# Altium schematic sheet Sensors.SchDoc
size A4
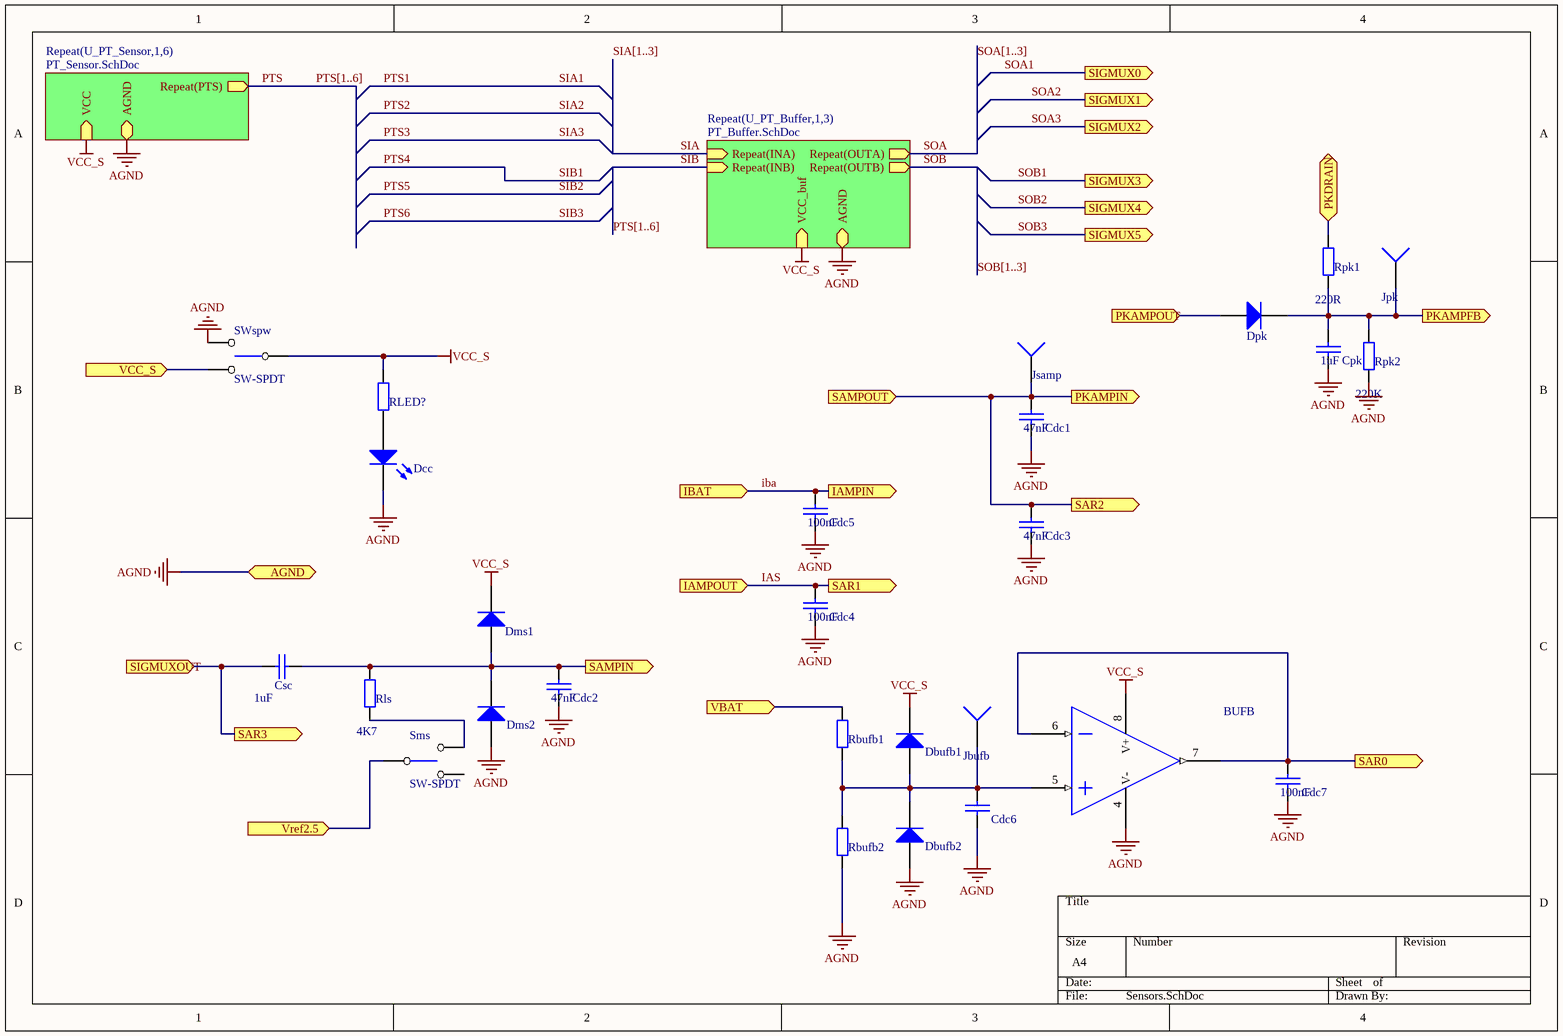
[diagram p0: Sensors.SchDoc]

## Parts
BUF  LT6221  [ECE-SO8]  (value not drawn)  (part B of 2)
Cdc1  47nF  [ECE-CAPC2012-0805SM]
Cdc2  47nF  [ECE-CAPC2012-0805SM]
Cdc3  47nF  [ECE-CAPC1608-0603SM]
Cdc4  100nF  [ECE-CAPC2012-0805SM]
Cdc5  100nF  [ECE-CAPC2012-0805SM]
Cdc6  100nF  [ECE-CAPC1608-0603SM]  (value not drawn)
Cdc7  100nF  [ECE-CAPC2012-0805SM]
Cpk  1uF  [ECE-CAPC1608-0603SM]
Csc  1uF  [ECE-CAPC2012-0805SM]
Dbufb1  1N4148  [ECE-DIO10.46-5.3x2.8TH]  (value not drawn)
Dbufb2  1N4148  [ECE-DIO10.46-5.3x2.8TH]  (value not drawn)
Dcc  LTST-C170KAKT  [ECE-LED2012-0805SM]  (value not drawn)
Dms1  1N4148  [ECE-DIO10.46-5.3x2.8TH]  (value not drawn)
Dms2  1N4148  [ECE-DIO10.46-5.3x2.8TH]  (value not drawn)
Dpk  1N4148  [ECE-DIO10.46-5.3x2.8TH]  (value not drawn)
Jbufb  TEST PIN  [ECE-HDR1TH]  (value not drawn)
Jpk  TEST PIN  [ECE-HDR1TH]  (value not drawn)
Jsamp  TEST PIN  [ECE-HDR1TH]  (value not drawn)
Rbufb1  47K  [ECE-RESC1608-0603SM]  (value not drawn)
Rbufb2  56K  [ECE-RESC2012-0805SM]  (value not drawn)
RLED?  270R  [ECE-RESC1608-0603SM]  (value not drawn)
Rls  4K7  [ECE-RESC2012-0805SM]
Rpk1  220R  [ECE-RESC1608-0603SM]
Rpk2  220K  [ECE-RESC1608-0603SM]
Sms  SW-SPDT  [SW-SPDT]
SWspw  SW-SPDT  [SW-SPDT]

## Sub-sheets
Repeat(U_PT_Buffer,1,3) = PT_Buffer.SchDoc: Repeat(INA) (in), Repeat(INB) (in), Repeat(OUTA) (out), Repeat(OUTB) (out), VCC_buf (in), AGND
Repeat(U_PT_Sensor,1,6) = PT_Sensor.SchDoc: Repeat(PTS) (out), VCC (in), AGND (bidir)

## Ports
AGND (bidir), IAMPIN (out), IAMPOUT (in), IBAT (in), PKAMPFB (out), PKAMPIN (out), PKAMPOUT (in), PKDRAIN (bidir), SAMPIN (out), SAMPOUT (in), SAR0 (out), SAR1 (out), SAR2 (out), SAR3 (out), SIGMUX0 (out), SIGMUX1 (out), SIGMUX2 (out), SIGMUX3 (out), SIGMUX4 (out), SIGMUX5 (out), SIGMUXOUT (in), VBAT (in), VCC_S (in), Vref2.5 (in)

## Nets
AGND: BUF.4(V-) Cdc1.2 Cdc2.2 Cdc3.2 Cdc4.2 Cdc5.2 Cdc6.2 Cdc7.2 Cpk.2 Dbufb2.1(A) Dcc.2(K) Dms2.1(A) Rbufb2.1 Rpk2.1 SWspw.3 ; port AGND, sheet Repeat(U_PT_Sensor,1,6)/AGND, sheet Repeat(U_PT_Buffer,1,3)/AGND
VCC_S: BUF.8(V+) Dbufb1.2(K) Dms1.2(K) RLED?.2 SWspw.2 ; sheet Repeat(U_PT_Sensor,1,6)/VCC, sheet Repeat(U_PT_Buffer,1,3)/VCC_buf
IAS: Cdc4.1 ; port IAMPOUT, port SAR1
iba: Cdc5.1 ; port IBAT, port IAMPIN
PKAMPFB: Cpk.1 Dpk.2(K) Jpk.1 Rpk1.1 Rpk2.2 ; port PKAMPFB
PKAMPIN: Cdc1.1 Cdc3.1 Jsamp.1 ; port SAMPOUT, port SAR2, port PKAMPIN
PKAMPOUT: Dpk.1(A) ; port PKAMPOUT
PKDRAIN: Rpk1.2 ; port PKDRAIN
SAMPIN: Cdc2.1 Csc.2 Dms1.1(A) Dms2.2(K) Rls.2 ; port SAMPIN
SAR0: BUF.6(IN2(-)) BUF.7(OUT2) Cdc7.1 ; port SAR0
SAR3: Csc.1 ; port SIGMUXOUT, port SAR3
VBAT: Rbufb1.2 ; port VBAT
VCC_S: SWspw.1 ; port VCC_S  [a separate net that carries the same name]
Vref2.5: Sms.2 ; port Vref2.5
NetBUF_5: BUF.5(IN2(+)) Cdc6.1 Dbufb1.1(A) Dbufb2.2(K) Jbufb.1 Rbufb1.1 Rbufb2.2
NetDcc_1: Dcc.1(A) RLED?.1
NetRls_1: Rls.1 Sms.1

Not connected (* = marked no-connect by the designer): Sms 3

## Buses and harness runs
bus PTS[1..6]
bus SIA[1..3]
bus SOA[1..3]
bus SOB[1..3]

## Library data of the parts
BUF = OPA000102: IC OPAMP LT6221 DUAL SM; Manufactuer: Linear Technology; Manufacturer-PN: LT6221CS8#TRPBF; Assembly Method: Surface Mount; Item Type: Item; Path: ece/ts/Lists/Stock Inventory
Cdc1 Cdc2 = CAP000522: CAP CER 47nF 50V X7R SM0805; Manufactuer: Samsung; Manufacturer-PN: CL21B473KBCNNNC; Assembly Method: Surface Mount; Item Type: Item; Path: ece/ts/Lists/Stock Inventory
Cdc3 = CAP000622: CAP CER 47nF 50V X7R SM0603; Manufactuer: Samsung; Manufacturer-PN: CL10B473KB8NNNC; Assembly Method: Surface Mount; Item Type: Item; Path: ece/ts/Lists/Stock Inventory
Cdc4 Cdc5 Cdc7 = CAP000524: CAP CER 100nF 50V X7R SM0805; Manufactuer: Samsung; Manufacturer-PN: CL21B104KBCNNNC; Assembly Method: Surface Mount; Item Type: Item; Path: ece/ts/Lists/Stock Inventory
Cdc6 = CAP000624: CAP CER 100nF 25V X7R SM0603; Manufactuer: Kemet; Manufacturer-PN: C0603C104K3RACTU; Assembly Method: Surface Mount; Item Type: Item; Path: ece/ts/Lists/Stock Inventory
Cpk = CAP000630: CAP CER 1uF 50V X7R SM0603; Manufactuer: Samsung; Manufacturer-PN: CL10B105KA8NNNC; Assembly Method: Surface Mount; Voltage/Current: 25V; Item Type: Item; Path: ece/ts/Lists/Stock Inventory
Csc = CAP000530: CAP CER 1uF 50V X7R SM0805; Manufactuer: Samsung; Manufacturer-PN: CL21B105KBFNNNE; Assembly Method: Surface Mount; Item Type: Item; Path: ece/ts/Lists/Stock Inventory
Dbufb1 Dbufb2 Dms1 Dms2 Dpk = DIO000005: Small Signal Diode 2A 100V TH; Manufactuer: VISHAY SEMICONDUCTOR; Assembly Method: Through hole; Voltage/Current: 2A-100V; Item Type: Item; Path: ece/ts/Lists/Stock Inventory
Dcc = DIO000105: LED RED ORANGE CLEAR 0805 SMD; Manufactuer: Lite-On Inc; Assembly Method: Surface Mount; Voltage/Current: 20mA; Item Type: Item; Path: ece/ts/Lists/Stock Inventory
Jbufb Jpk Jsamp = CON000017: Value: 1 way; Assembly Method: Through hole; Item Type: Item; Path: ece/ts/Lists/Stock Inventory
Rbufb1 = RES000158: RES CER 47K 1608 SM; Manufactuer: Yageo; Manufacturer-PN: RC0603FR-0747KL; Assembly Method: Surface Mount; Voltage/Current: 1/10W; Item Type: Item; Path: ece/ts/Lists/Stock Inventory
Rbufb2 = RES000559: RES CER 56K 2012 SM; Assembly Method: Surface Mount; Voltage/Current: 1/8W; Item Type: Item; Path: ece/ts/Lists/Stock Inventory
RLED? = RES000131: RES CER 270R 1608 SM; Assembly Method: Surface Mount; Voltage/Current: 1/10W; Item Type: Item; Path: ece/ts/Lists/Stock Inventory
Rls = RES000546: RES CER 4K7 2012 SM; Assembly Method: Surface Mount; Voltage/Current: 1/8W; Item Type: Item; Path: ece/ts/Lists/Stock Inventory
Rpk1 = RES000130: RES CER 220R 1608 SM; Manufactuer: Samsung; Manufacturer-PN: RC1608F221CS; Assembly Method: Surface Mount; Voltage/Current: 1/10W; Item Type: Item; Path: ece/ts/Lists/Stock Inventory
Rpk2 = RES000166: RES CER 220K 1608 SM; Manufactuer: Yageo; Manufacturer-PN: RC0603FR-07220KL; Assembly Method: Surface Mount; Voltage/Current: 1/10W; Item Type: Item; Path: ece/ts/Lists/Stock Inventory
Sms SWspw = SW-SPDT: Toggle Switch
